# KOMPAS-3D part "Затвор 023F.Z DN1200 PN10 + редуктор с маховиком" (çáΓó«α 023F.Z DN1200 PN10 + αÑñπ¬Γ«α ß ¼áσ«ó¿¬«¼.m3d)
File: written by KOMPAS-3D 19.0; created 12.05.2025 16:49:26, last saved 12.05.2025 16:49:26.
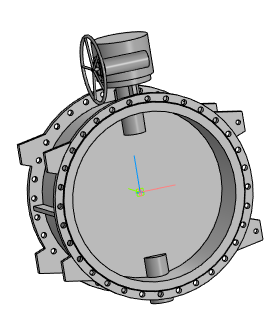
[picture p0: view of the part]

Document properties: Полное имя файла: Затвор 023F.Z DN1200 PN10 + редуктор с маховиком.a3d

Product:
- Part/product: Затвор 023F.Z DN1200 PN10 + редуктор с маховиком
    Масса: 2060.81

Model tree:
1. Операция без истории:1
